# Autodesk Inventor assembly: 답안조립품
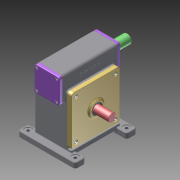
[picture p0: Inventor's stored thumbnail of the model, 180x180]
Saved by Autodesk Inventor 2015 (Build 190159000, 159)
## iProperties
Created: 2025-06
Part Number: 답안조립품
Document SubType Name: Assembly
Designer: 104
Author: 104
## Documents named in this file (13)
- C:\Users\104\Desktop\750603V1014\답안조립품.iam
- C:\Users\104\Documents\Inventor\6각 구멍붙이 볼트 M6x12.ipt
- C:\Users\104\Desktop\750603V1014\가져온 구성요소\6각 구멍붙이 볼트 M8x20\6각 구멍붙이 볼트 M8x20.ipt
- C:\Users\104\Desktop\750603V1014\가져온 구성요소\깊은 홈 볼 베어링 6206\깊은 홈 볼 베어링 6206.ipt
- C:\Users\104\Desktop\750603V1014\가져온 구성요소\깊은 홈 볼 베어링 6209\깊은 홈 볼 베어링 6209.ipt
- C:\Users\104\Desktop\750603V1014\가져온 구성요소\뒷커버\뒷커버.ipt
- C:\Users\104\Desktop\750603V1014\본체.ipt
- C:\Users\104\Desktop\750603V1014\가져온 구성요소\앞커버\앞커버.ipt
- C:\Users\104\Desktop\750603V1014\가져온 구성요소\오일 실 30 42 7\오일 실 30 42 7.ipt
- C:\Users\104\Desktop\750603V1014\가져온 구성요소\오일 실 35 55 11\오일 실 35 55 11.ipt
- C:\Users\104\Desktop\750603V1014\가져온 구성요소\웜 샤프트\웜 샤프트.ipt
- C:\Users\104\Desktop\750603V1014\가져온 구성요소\웜 휠 커버\웜 휠 커버.ipt
- C:\Users\104\Desktop\750603V1014\가져온 구성요소\웜 휠\웜 휠.ipt
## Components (12 placed, 2 different names)
1. 6각 구멍붙이 볼트 M6x12:1
2. 6각 구멍붙이 볼트 M8x20:1
3. 6각 구멍붙이 볼트 M8x20:2
4. 6각 구멍붙이 볼트 M8x20:3
5. 6각 구멍붙이 볼트 M8x20:4
6. 6각 구멍붙이 볼트 M6x12:2
7. 6각 구멍붙이 볼트 M6x12:3
8. 6각 구멍붙이 볼트 M6x12:4
9. 6각 구멍붙이 볼트 M6x12:5
10. 6각 구멍붙이 볼트 M6x12:6
11. 6각 구멍붙이 볼트 M6x12:7
12. 6각 구멍붙이 볼트 M6x12:8
